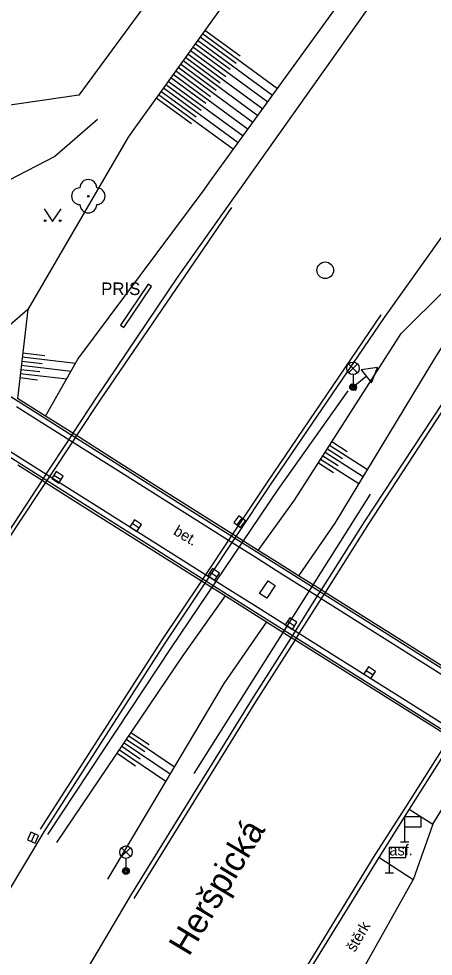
# Model space of a CAD drawing. Extents: x -599951 to -598963, y -1164095 to -1162939.
# Drawn here: x -599064.1 to -599039.4, y -1163421.1 to -1163365 of the extents above; entities that cross this region are included whole.
import ezdxf

# ---------------------------------------------------------------- set-up
doc = ezdxf.new("R2010")
doc.units = 0
for name, color, linetype in [('Level 10', 7, 'Continuous'), ('Level 11', 7, 'Continuous'), ('Level 14', 7, 'Continuous'), ('Level 15', 7, 'Continuous'), ('Level 22', 7, 'Continuous'), ('Level 24', 7, 'Continuous'), ('Level 27', 7, 'Continuous'), ('Level 33', 7, 'Continuous'), ('Level 34', 7, 'Continuous'), ('Level 36', 7, 'Continuous'), ('Level 40', 7, 'Continuous'), ('Level 41', 7, 'Continuous'), ('Level 50', 7, 'Continuous'), ('Level 7', 7, 'Continuous'), ('Level 9', 7, 'Continuous')]:
    doc.layers.add(name, color=color, linetype=linetype)

msp = doc.modelspace()

# ---------------------------------------------------------------- linework, layer by layer
at = {"layer": 'Level 10'}
for points in [[(-599018.74, -1163330.48), (-599029.98, -1163345.58), (-599051.63, -1163376.15), (-599054.67, -1163380.47), (-599059.5, -1163387.61)], [(-599005.84, -1163340.22), (-599014.08, -1163351.62), (-599024.08, -1163365.93), (-599031.83, -1163377.36), (-599043.5, -1163395.08), (-599046.08, -1163399.14)], [(-599051.15, -1163395.95), (-599049.1, -1163392.86), (-599042.29, -1163382.85)], [(-599059.5, -1163387.61), (-599060.92, -1163389.78)], [(-599061.16, -1163390.15), (-599062.52, -1163392.23)], [(-599060.92, -1163389.78), (-599061.16, -1163390.15)], [(-599062.52, -1163392.23), (-599062.75, -1163392.59)], [(-599062.75, -1163392.59), (-599064.44, -1163395.17), (-599065.68, -1163397.03)], [(-599052.77, -1163398.38), (-599051.39, -1163396.31)], [(-599051.39, -1163396.31), (-599051.15, -1163395.95)], [(-599053.01, -1163398.74), (-599052.77, -1163398.38)], [(-599117.65, -1163521.09), (-599114.44, -1163513.27), (-599110.34, -1163503.76), (-599106.54, -1163495.23), (-599103.39, -1163488.42), (-599090.5, -1163462.37), (-599077.66, -1163438.76), (-599074.812, -1163433.995), (-599062.63, -1163413.61), (-599055.4, -1163402.34), (-599053.01, -1163398.74)], [(-599046.08, -1163399.14), (-599046.31, -1163399.51)], [(-599046.31, -1163399.51), (-599047.62, -1163401.62)], [(-599047.62, -1163401.62), (-599047.86, -1163401.99)], [(-599047.86, -1163401.99), (-599050.23, -1163405.73), (-599057.47, -1163417.43), (-599062.46, -1163425.89), (-599072.58, -1163443.64), (-599087.83, -1163474.25), (-599089.79, -1163478.58), (-599092.69, -1163484.97), (-599097.7, -1163496.33)], [(-599038.17, -1163408.08), (-599040.82, -1163412.27)], [(-599040.82, -1163412.27), (-599042.63, -1163415.16)], [(-599042.63, -1163415.16), (-599047.62, -1163423.27), (-599059.83, -1163444.92), (-599062.215, -1163449.439), (-599062.4, -1163449.79)]]:
    msp.add_lwpolyline(points, dxfattribs=at)
at = {"layer": 'Level 11'}
for points in [[(-599042.29, -1163382.85), (-599038.78, -1163377.93), (-599038.14, -1163377.03), (-599037.99, -1163376.82), (-599036.25, -1163374.28), (-599035.98, -1163373.88), (-599033.42, -1163370.14), (-599033.38, -1163370.1), (-599032.63, -1163369.06), (-599031.08, -1163366.92), (-599030.98, -1163366.79), (-599028.55, -1163363.45), (-599026.42, -1163360.5), (-599024.91, -1163358.42), (-599024.58, -1163357.96), (-599022.23, -1163354.74), (-599019.57, -1163351.07), (-599018.33, -1163349.36), (-599017.34, -1163347.99), (-599012.88, -1163341.85), (-599011.76, -1163340.31), (-599009.65, -1163337.4)], [(-599023.85, -1163366.07), (-599031.59, -1163377.53), (-599037.56, -1163386.5), (-599043.24, -1163395.2), (-599045.84, -1163399.3)], [(-599051.44, -1163376.28), (-599059.24, -1163387.72), (-599060.7, -1163389.92)], [(-599042.5, -1163382.69), (-599049.3, -1163392.71), (-599051.37, -1163395.81)], [(-599062.54, -1163388.75), (-599064.23, -1163387.69)], [(-599063.99, -1163391.3), (-599069.13, -1163388.05)], [(-599064.29, -1163388.17), (-599062.76, -1163389.14)], [(-599060.92, -1163389.78), (-599062.54, -1163388.75)], [(-599062.76, -1163389.14), (-599061.16, -1163390.15)], [(-599061.16, -1163390.15), (-599060.94, -1163390.29)], [(-599060.7, -1163389.92), (-599060.94, -1163390.29)], [(-599060.71, -1163389.92), (-599060.92, -1163389.78)], [(-599051.37, -1163395.81), (-599057.98, -1163391.64), (-599060.7, -1163389.92)], [(-599060.94, -1163390.29), (-599062.31, -1163392.36)], [(-599060.94, -1163390.29), (-599058.21, -1163392.01)], [(-599062.52, -1163392.23), (-599063.99, -1163391.3)], [(-599064.2, -1163391.67), (-599062.75, -1163392.59)], [(-599062.31, -1163392.36), (-599062.55, -1163392.72)], [(-599062.31, -1163392.36), (-599062.52, -1163392.23)], [(-599059.68, -1163394.02), (-599062.31, -1163392.36)], [(-599058.21, -1163392.01), (-599051.61, -1163396.17)], [(-599062.55, -1163392.72), (-599064.24, -1163395.28), (-599072.03, -1163407.41)], [(-599062.75, -1163392.59), (-599062.55, -1163392.72)], [(-599062.55, -1163392.72), (-599059.93, -1163394.37)], [(-599052.98, -1163398.24), (-599059.68, -1163394.02)], [(-599059.93, -1163394.37), (-599053.23, -1163398.61)], [(-599051.61, -1163396.17), (-599052.98, -1163398.24)], [(-599051.37, -1163395.81), (-599051.61, -1163396.17)], [(-599051.61, -1163396.17), (-599051.39, -1163396.31)], [(-599051.39, -1163396.31), (-599050.08, -1163397.13)], [(-599051.15, -1163395.95), (-599051.37, -1163395.81)], [(-599049.83, -1163396.78), (-599051.15, -1163395.95)], [(-599047.42, -1163398.3), (-599048.53, -1163397.6), (-599049.83, -1163396.78)], [(-599050.08, -1163397.13), (-599048.74, -1163397.98)], [(-599048.74, -1163397.98), (-599047.67, -1163398.66)], [(-599052.98, -1163398.24), (-599053.23, -1163398.61)], [(-599052.77, -1163398.38), (-599052.98, -1163398.24)], [(-599051.53, -1163399.16), (-599052.77, -1163398.38)], [(-599046.08, -1163399.14), (-599047.42, -1163398.3)], [(-599053.23, -1163398.61), (-599055.61, -1163402.18), (-599062.86, -1163413.45)], [(-599053.23, -1163398.61), (-599053.01, -1163398.74)], [(-599053.01, -1163398.74), (-599051.79, -1163399.51)], [(-599050.06, -1163400.08), (-599051.53, -1163399.16)], [(-599049.75, -1163399.36), (-599049.24, -1163398.61)], [(-599048.82, -1163398.89), (-599049.33, -1163399.64)], [(-599049.24, -1163398.61), (-599048.82, -1163398.89)], [(-599047.67, -1163398.66), (-599046.31, -1163399.51)], [(-599045.84, -1163399.3), (-599046.08, -1163399.14)], [(-599051.79, -1163399.51), (-599049.34, -1163401.06)], [(-599049.33, -1163399.64), (-599049.75, -1163399.36)], [(-599046.07, -1163399.66), (-599047.4, -1163401.76)], [(-599046.31, -1163399.51), (-599046.07, -1163399.66)], [(-599045.84, -1163399.3), (-599046.07, -1163399.66)], [(-599046.07, -1163399.66), (-599037.78, -1163404.89)], [(-599036.57, -1163405.13), (-599037.57, -1163404.5), (-599045.84, -1163399.3)], [(-599049.09, -1163400.69), (-599050.06, -1163400.08)], [(-599047.62, -1163401.62), (-599049.09, -1163400.69)], [(-599049.34, -1163401.06), (-599047.86, -1163401.99)], [(-599047.4, -1163401.76), (-599047.63, -1163402.13)], [(-599047.4, -1163401.76), (-599047.62, -1163401.62)], [(-599038.13, -1163407.59), (-599039.17, -1163406.93), (-599047.4, -1163401.76)], [(-599047.63, -1163402.13), (-599049.99, -1163405.85), (-599057.26, -1163417.61)], [(-599047.86, -1163401.99), (-599047.63, -1163402.13)], [(-599047.63, -1163402.13), (-599039.4, -1163407.3), (-599038.36, -1163407.95)], [(-599047.82, -1163423.14), (-599042.84, -1163415), (-599041.02, -1163412.14), (-599038.36, -1163407.95)], [(-599040.82, -1163412.27), (-599039.4, -1163413.16)], [(-599039.4, -1163413.16), (-599040.57, -1163416.48)], [(-599040.57, -1163416.48), (-599042.63, -1163415.16)]]:
    msp.add_lwpolyline(points, dxfattribs=at)
at = {"layer": 'Level 14'}
for points in [[(-598963.215, -1163244.459), (-598964.63, -1163246.57), (-598966.75, -1163249.87), (-598970.92, -1163255.75), (-598983.23, -1163271.56), (-598995.54, -1163287.35), (-598999.79, -1163293.24), (-599006.53, -1163302.72), (-599013.36, -1163311.25), (-599016.9, -1163315.62), (-599023.69, -1163324.85), (-599057.16, -1163371.44), (-599057.61, -1163372.07), (-599063.61, -1163382.37), (-599064.23, -1163387.69)], [(-599062.54, -1163388.75), (-599060.61, -1163385.35), (-599053.07, -1163375.22), (-599052.74, -1163374.76), (-599019.09, -1163328.31), (-599010.56, -1163316.77), (-599002.53, -1163305.72), (-599000.34, -1163302.8), (-598990.84, -1163290.5), (-598988.07, -1163287.07)], [(-599049.83, -1163396.78), (-599047.67, -1163393.77), (-599041.29, -1163383.81), (-599033.32, -1163375.89)], [(-599033.32, -1163375.89), (-599039.25, -1163385.21), (-599045.25, -1163395.16), (-599047.42, -1163398.3)], [(-599063.61, -1163382.37), (-599067.31, -1163385.59), (-599067.37, -1163385.7)], [(-599061.87, -1163414.26), (-599054.33, -1163403.06), (-599051.79, -1163399.51)], [(-599049.34, -1163401.06), (-599051.89, -1163404.75), (-599058.85, -1163416.45)], [(-599039.4, -1163413.16), (-599036.79, -1163408.94)], [(-599045.18, -1163424.7), (-599040.57, -1163416.48)]]:
    msp.add_lwpolyline(points, dxfattribs=at)
at = {"layer": 'Level 15'}
for points in [[(-599048.69, -1163369.17), (-599053.16, -1163365.88)], [(-599050.92, -1163367.22), (-599053.02, -1163365.68)], [(-599051.51, -1163368.02), (-599053.61, -1163366.49)], [(-599048.98, -1163369.58), (-599053.46, -1163366.29)], [(-599051.15, -1163367.67), (-599053.31, -1163366.08)], [(-599049.57, -1163370.39), (-599054.04, -1163367.1)], [(-599051.78, -1163368.45), (-599053.89, -1163366.9)], [(-599049.27, -1163369.98), (-599053.75, -1163366.69)], [(-599052.34, -1163369.27), (-599054.48, -1163367.71)], [(-599049.86, -1163370.79), (-599054.33, -1163367.5)], [(-599052.11, -1163368.83), (-599054.19, -1163367.3)], [(-599050.44, -1163371.6), (-599054.91, -1163368.32)], [(-599052.68, -1163369.65), (-599054.77, -1163368.11)], [(-599050.15, -1163371.19), (-599054.62, -1163367.91)], [(-599050.74, -1163372), (-599055.21, -1163368.73)], [(-599052.97, -1163370.05), (-599055.06, -1163368.52)], [(-599053.55, -1163370.87), (-599055.65, -1163369.33)], [(-599051.03, -1163372.41), (-599055.5, -1163369.13)], [(-599053.25, -1163370.47), (-599055.35, -1163368.93)], [(-599053.83, -1163371.28), (-599055.93, -1163369.73)], [(-599051.32, -1163372.81), (-599055.79, -1163369.53)], [(-599063.91, -1163384.96), (-599062.59, -1163385.12)], [(-599063.97, -1163385.46), (-599062.74, -1163385.61)], [(-599063.94, -1163385.21), (-599060.75, -1163385.59)], [(-599064.06, -1163386.21), (-599061.28, -1163386.53)], [(-599064.03, -1163385.96), (-599062.88, -1163386.09)], [(-599064, -1163385.71), (-599061.01, -1163386.06)], [(-599064.09, -1163386.45), (-599063.02, -1163386.58)], [(-599045.7, -1163390.7), (-599044.8, -1163391.28)], [(-599045.57, -1163390.49), (-599043.31, -1163391.94)], [(-599045.43, -1163390.28), (-599044.53, -1163390.86)], [(-599045.97, -1163391.12), (-599045.06, -1163391.71)], [(-599045.84, -1163390.91), (-599043.56, -1163392.37)], [(-599046.24, -1163391.54), (-599045.33, -1163392.13)], [(-599046.11, -1163391.33), (-599043.82, -1163392.79)], [(-599057.71, -1163408.09), (-599056.62, -1163408.82)], [(-599057.57, -1163407.88), (-599054.84, -1163409.72)], [(-599057.44, -1163407.67), (-599056.35, -1163408.4)], [(-599057.99, -1163408.5), (-599056.89, -1163409.25)], [(-599057.85, -1163408.29), (-599055.1, -1163410.15)], [(-599058.27, -1163408.92), (-599057.16, -1163409.67)], [(-599058.13, -1163408.71), (-599055.36, -1163410.58)]]:
    msp.add_lwpolyline(points, dxfattribs=at)
at = {"layer": 'Level 22'}
msp.add_circle((-599059.99, -1163375.6), 0.05, dxfattribs=at)
for centre, start, end in [((-599059.99, -1163375.1), 0, 180), ((-599060.49, -1163375.6), 90, 270), ((-599059.49, -1163375.6), 270, 90), ((-599059.99, -1163376.1), 180, 0)]:
    msp.add_arc(centre, 0.5, start, end, dxfattribs=at)
at = {"layer": 'Level 24'}
for points in [[(-599056.42, -1163380.85), (-599058.07, -1163383.31)], [(-599057.87, -1163383.45), (-599056.22, -1163380.99)], [(-599056.22, -1163380.99), (-599056.42, -1163380.85)], [(-599058.07, -1163383.31), (-599057.87, -1163383.45)]]:
    msp.add_lwpolyline(points, dxfattribs=at)
at = {"layer": 'Level 27'}
for p, q in [((-599062.04, -1163392.274), (-599061.62, -1163392.546)), ((-599057.37, -1163395.164), (-599056.95, -1163395.436)), ((-599051.092, -1163395.259), (-599050.788, -1163394.861)), ((-599052.71, -1163398.084), (-599052.29, -1163398.356)), ((-599048.08, -1163401.024), (-599047.66, -1163401.296)), ((-599043.39, -1163403.964), (-599042.97, -1163404.236)), ((-599063.392, -1163414.198), (-599063.188, -1163413.742))]:
    msp.add_line(p, q, dxfattribs=at)
for points in [[(-599062.176, -1163392.484), (-599061.756, -1163392.756), (-599061.484, -1163392.336), (-599061.904, -1163392.064)], [(-599057.506, -1163395.374), (-599057.086, -1163395.646), (-599056.814, -1163395.226), (-599057.234, -1163394.954)], [(-599050.893, -1163395.41), (-599050.59, -1163395.013), (-599050.987, -1163394.71), (-599051.29, -1163395.107)], [(-599052.846, -1163398.294), (-599052.426, -1163398.566), (-599052.154, -1163398.146), (-599052.574, -1163397.874)], [(-599048.216, -1163401.234), (-599047.796, -1163401.506), (-599047.524, -1163401.086), (-599047.944, -1163400.814)], [(-599043.526, -1163404.174), (-599043.106, -1163404.446), (-599042.834, -1163404.026), (-599043.254, -1163403.754)], [(-599063.163, -1163414.3), (-599062.96, -1163413.843), (-599063.417, -1163413.64), (-599063.62, -1163414.097)]]:
    msp.add_lwpolyline(points, close=True, dxfattribs=at)
msp.add_circle((-599045.83, -1163380.03), 0.5, dxfattribs=at)
at = {"layer": 'Level 33'}
for p, q in [((-599044.435, -1163386.16), (-599043.905, -1163385.63)), ((-599044.435, -1163385.63), (-599043.905, -1163386.16)), ((-599044.17, -1163386.27), (-599044.17, -1163387.02)), ((-599058.005, -1163415.1), (-599057.475, -1163414.57)), ((-599058.005, -1163414.57), (-599057.475, -1163415.1)), ((-599057.74, -1163415.21), (-599057.74, -1163415.96))]:
    msp.add_line(p, q, dxfattribs=at)
for centre, radius in [((-599044.17, -1163385.895), 0.375), ((-599044.17, -1163387.02), 0.2), ((-599044.17, -1163387.02), 0.145), ((-599044.17, -1163387.02), 0.0876), ((-599057.74, -1163414.835), 0.375), ((-599057.74, -1163415.96), 0.2), ((-599057.74, -1163415.96), 0.145), ((-599057.74, -1163415.96), 0.0876)]:
    msp.add_circle(centre, radius, dxfattribs=at)
at = {"layer": 'Level 34'}
for p, q in [((-599044.327, -1163386.825), (-599044.013, -1163387.215)), ((-599043.378, -1163386.381), (-599044.17, -1163387.02)), ((-599041.09, -1163413.31), (-599041.09, -1163414.21)), ((-599041.34, -1163414.21), (-599040.84, -1163414.21)), ((-599042.01, -1163415.16), (-599042.01, -1163416.06)), ((-599042.26, -1163416.06), (-599041.76, -1163416.06))]:
    msp.add_line(p, q, dxfattribs=at)
for points in [[(-599043.692, -1163385.992), (-599043.064, -1163386.77), (-599042.704, -1163385.837)], [(-599041.09, -1163413.31), (-599040.09, -1163413.31), (-599040.09, -1163412.71), (-599041.09, -1163412.71)], [(-599042.01, -1163415.16), (-599041.01, -1163415.16), (-599041.01, -1163414.56), (-599042.01, -1163414.56)]]:
    msp.add_lwpolyline(points, close=True, dxfattribs=at)
at = {"layer": 'Level 36'}
msp.add_lwpolyline([(-599062.62, -1163376.36), (-599062.12, -1163377.11), (-599061.62, -1163376.36)], dxfattribs=at)
for centre in [(-599062.57, -1163377.06), (-599061.671, -1163377.06)]:
    msp.add_circle(centre, 0.05, dxfattribs=at)
at = {"layer": 'Level 7'}
for points in [[(-598963.215, -1163238.039), (-599005.05, -1163293.93), (-599028.2, -1163325.47), (-599039.19, -1163340.45), (-599060.55, -1163369.55), (-599087.59, -1163373.49)], [(-599059.44, -1163371.02), (-599061.99, -1163373.22), (-599064.75, -1163374.66), (-599070.15, -1163375.42)]]:
    msp.add_lwpolyline(points, dxfattribs=at)
at = {"layer": 'Level 9'}
for points in [[(-599022.47, -1163414.18), (-599025.72, -1163412.12), (-599037.6, -1163404.64), (-599048.59, -1163397.72), (-599054.62, -1163393.93), (-599058.05, -1163391.76), (-599071.15, -1163383.47), (-599074.39, -1163381.45)], [(-599078.33, -1163384.69), (-599076.03, -1163384.07), (-599072.77, -1163386.09), (-599059.84, -1163394.26), (-599050.37, -1163400.24), (-599039.32, -1163407.2), (-599027.36, -1163414.75)], [(-599044.49, -1163387.23), (-599048.66, -1163393.14), (-599055.03, -1163402.59), (-599062.42, -1163413.78)], [(-599053.66, -1163410.12), (-599043.12, -1163393.43)]]:
    msp.add_lwpolyline(points, dxfattribs=at)

# ---------------------------------------------------------------- texts
at = {"layer": 'Level 40'}
for s, rotation, p in [('bet.', 329.31, (-599054.96, -1163395.8)), ('štěrk', 59.8, (-599044.06, -1163420.85))]:
    msp.add_text(s, height=0.65, rotation=rotation, dxfattribs=at).set_placement(p)
msp.add_text('asf.', height=0.65, dxfattribs=at).set_placement((-599042, -1163415.03))
at = {"layer": 'Level 41'}
msp.add_text('PRIS', height=0.75, dxfattribs=at).set_placement((-599059.22, -1163381.51))
at = {"layer": 'Level 50'}
msp.add_text('Heršpická', height=1.5, rotation=58.9445, dxfattribs=at).set_placement((-599053.981, -1163421.117))

doc.saveas('drawing.dxf')
